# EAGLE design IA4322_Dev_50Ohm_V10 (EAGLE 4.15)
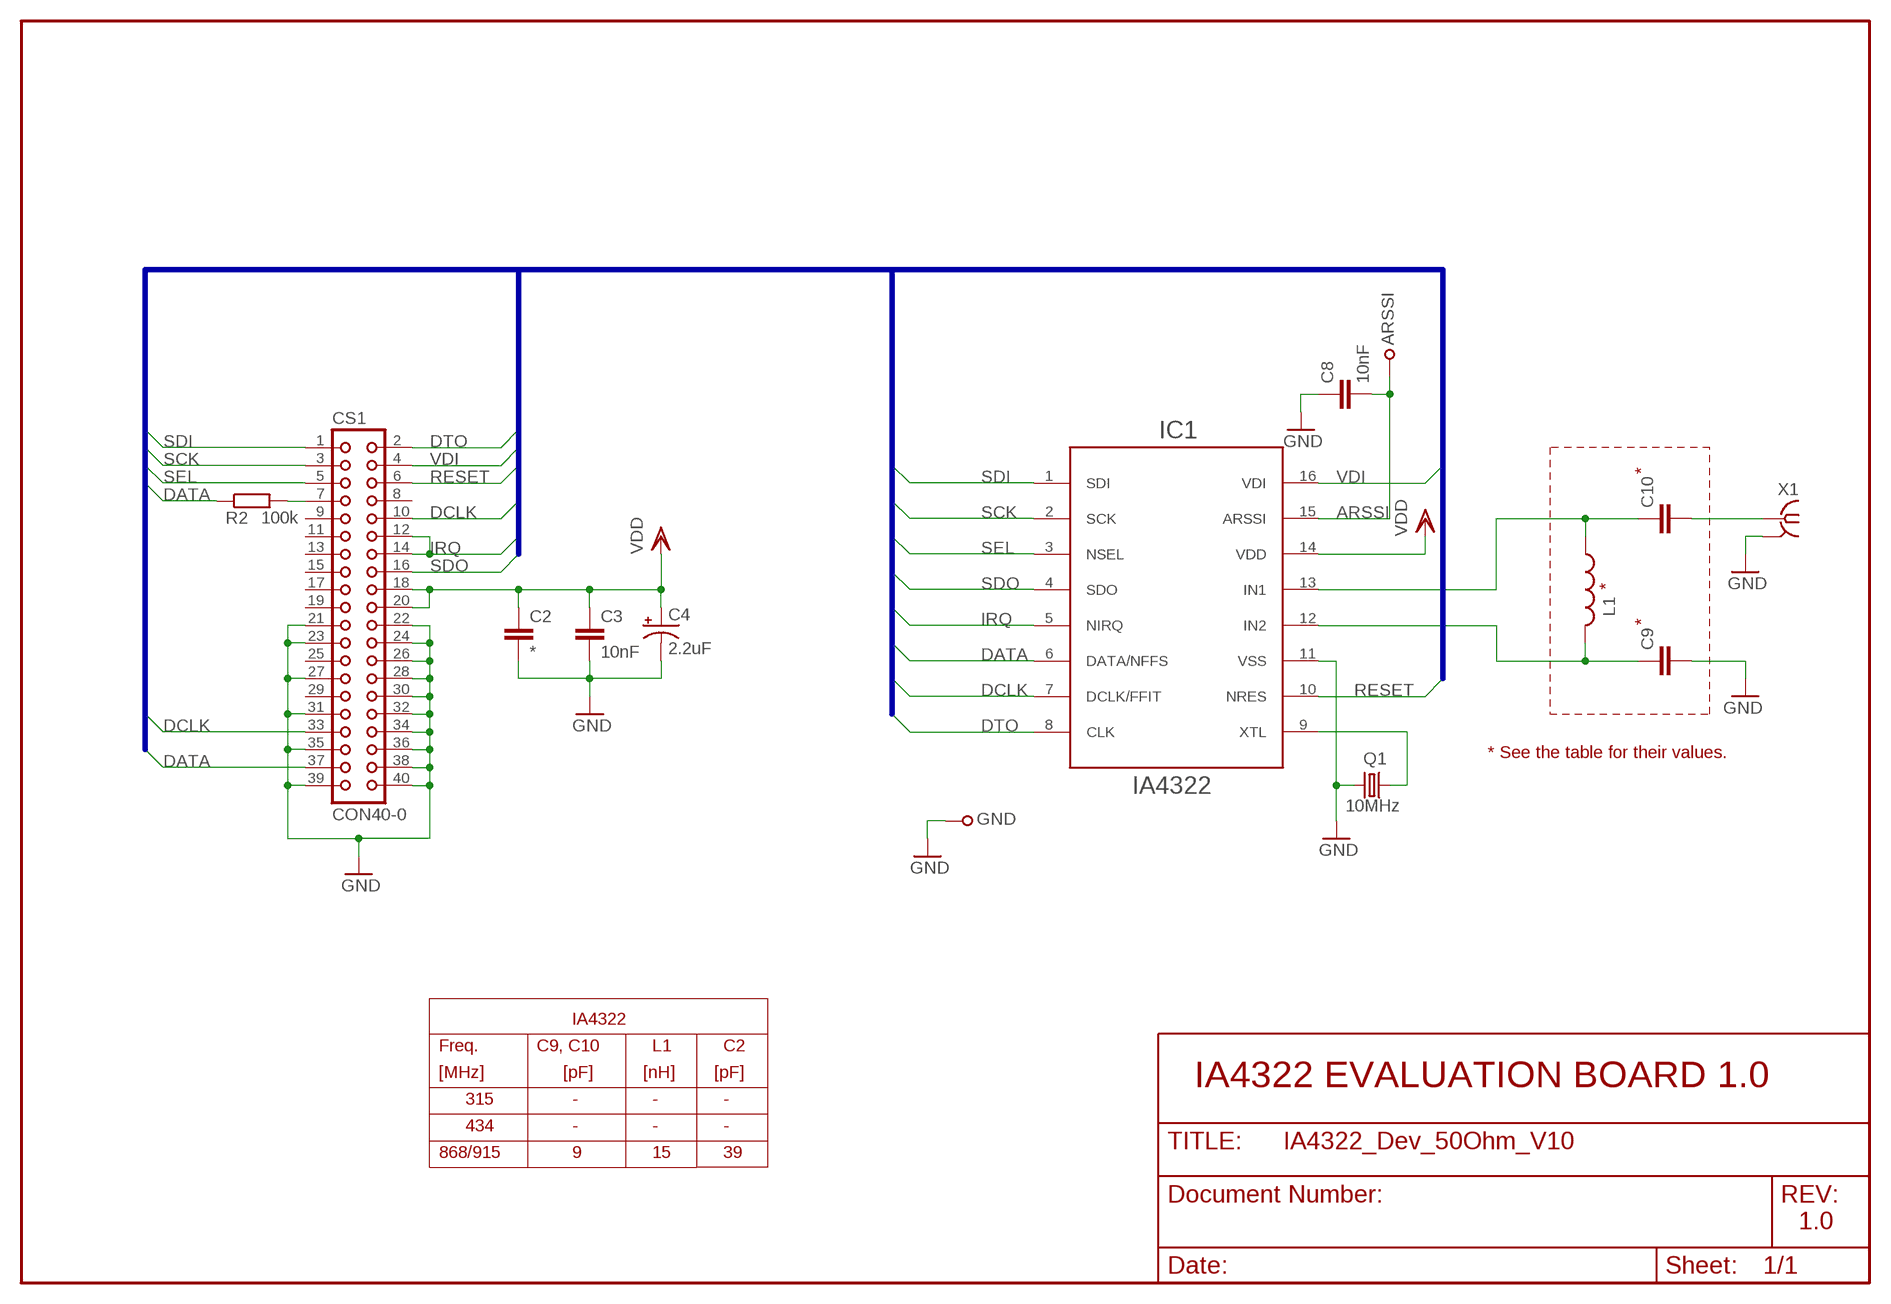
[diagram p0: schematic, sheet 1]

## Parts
ARSSI  TESTPOINT  TESTPOINT39MIL  [TESTPOINT1,0]
C2  *  C-EUC0603  [C0603]
C3  10nF  C-EUC0603  [C0603]
C4  2.2uF  CPOL-USA/3216-18R  [A/3216-18R]
C8  10nF  C-EUC0603  [C0603]
C9  C-EUC0603  [C0603]
C10  C-EUC0603  [C0603]
CS1  CON40-0  [PANDUIT-057-040-0-INTEGRATION]
GND  TESTPOINT39MIL  [TESTPOINT1,0]
IC1  IA4322  RITATSSOP-16(NEW)  [TSSOP-16(NEW)]
L1  INDUCTCOILCRAFT-0603  [L1608]
Q1  10MHz  CRYTALSM49  [SM49]
R2  100k  R-EU_R0603  [R0603]
X1  BU-SMA-H  [BU-SMA-H]

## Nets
ARSSI: ARSSI.1 C8.2 IC1.15(ARSSI)
DATA: CS1.37 IC1.6(DATA/NFFS) R2.1
DCLK: CS1.10 CS1.33 IC1.7(DCLK/FFIT)
DTO: CS1.2 IC1.8(CLK)
GND: C2.2 C3.2 C4.- C8.1 C9.2 CS1.21 CS1.22 CS1.23 CS1.24 CS1.26 CS1.27 CS1.28 CS1.30 CS1.31 CS1.32 CS1.34 CS1.35 CS1.36 CS1.38 CS1.39 CS1.40 GND.1 IC1.11(VSS) Q1.2 X1.2(GND)
IRQ: CS1.12 CS1.14 IC1.5(NIRQ)
N$1: CS1.7 R2.2
N$2: C10.1 IC1.13(IN1) L1.2
N$3: C9.1 IC1.12(IN2) L1.1
N$4: IC1.9(XTL) Q1.1
N$8: C10.2 X1.1
RESET: CS1.6 IC1.10(NRES)
SCK: CS1.3 IC1.2(SCK)
SDI: CS1.1 IC1.1(SDI)
SDO: CS1.16 IC1.4(SDO)
SEL: CS1.5 IC1.3(NSEL)
VDD: C2.1 C3.1 C4.+ CS1.18 CS1.20 IC1.14(VDD)
VDI: CS1.4 IC1.16(VDI)
Unconnected: CS1.8 CS1.9 CS1.11 CS1.13 CS1.15 CS1.17 CS1.19 CS1.25 CS1.29

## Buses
B$1

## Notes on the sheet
- *
- *
- *
- * See the table for their values.
- IA4322
- Freq. | C9, C10 | L1 | C2
- [MHz] | [pF] | [nH] | [pF]
- IA4322 EVALUATION BOARD 1.0
- 315 | - | - | -
- 434 | - | - | -
- 868/915 | 9 | 15 | 39
- 1.0

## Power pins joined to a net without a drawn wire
GND: X1.3(GND) X1.4(GND) X1.5(GND)

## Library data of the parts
ARSSI GND = lve:TESTPOINT
C2 C3 C8-C10 = rcl:C-EU: CAPACITOR, European symbol
C4 = rcl:CPOL-US: POLARIZED CAPACITOR, American symbol
CS1 = lve:CON40
IC1 = lve:RITA: RITA
L1 = lve:INDUCT
Q1 = crystal:CRYTAL: CRYSTAL
R2 = rcl:R-EU_: RESISTOR, European symbol
X1 = con-coax:BU-SMA-H: FEMALE SMA CONNECTOR Radiall distributor RS 193-9325

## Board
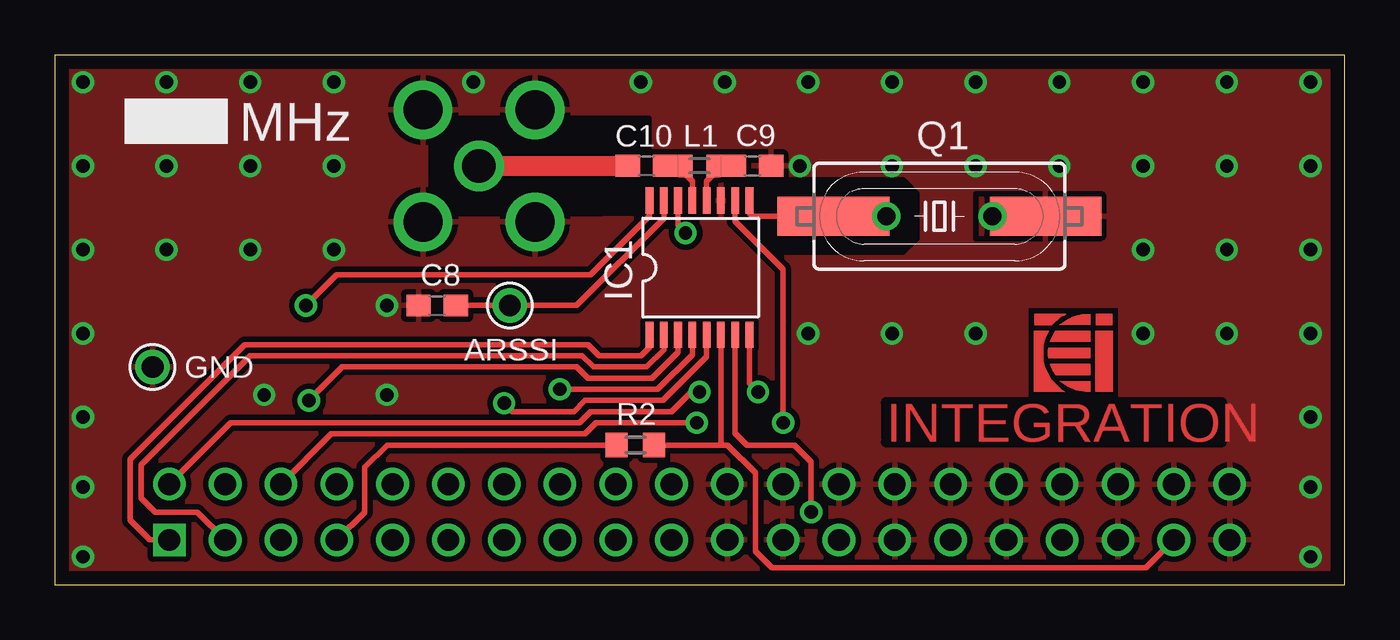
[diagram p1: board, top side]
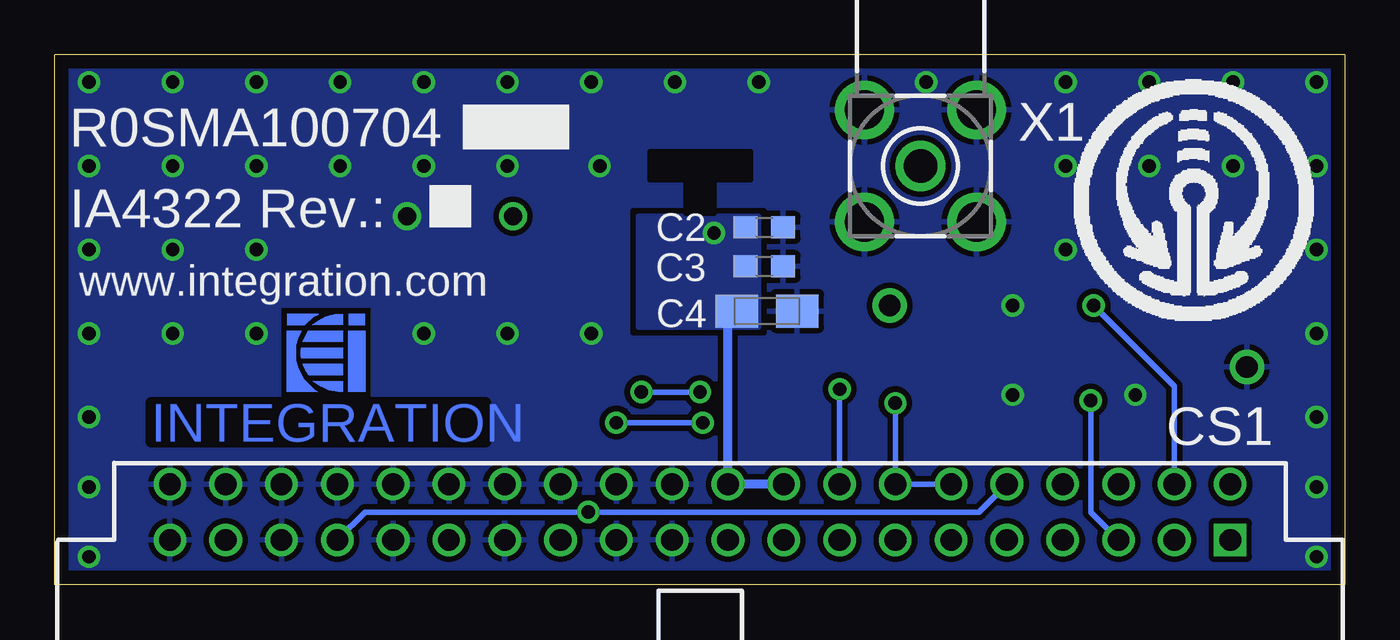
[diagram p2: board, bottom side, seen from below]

Size 58.7 x 24.1 mm. Coordinates in mm from the lower left corner, seen from the top.
Outline: 0,0 58.7,0 58.7,24.1 0,24.1 0,0
Copper layers (1*16): Top 0.035mm / dielectric 1.5mm / Bottom 0.035mm
Design rules "default_INTEGRATION": minimum track width 10mil, minimum drill 24mil, track to track 10mil, track to pad 10mil, pad to pad 10mil, via to via 10mil, smd to smd 10mil, copper to edge 25mil, drill to drill 8mil, minimum pad ring 8mil, minimum via ring 8mil, stop-mask expansion 4mil, vias tented up to drill 24mil, thermal gap 10mil
tRestrict: area 17,16.8 to 24.9,21.3; 14 lines
bRestrict: 10 lines

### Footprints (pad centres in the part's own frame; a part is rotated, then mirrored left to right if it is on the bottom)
TESTPOINT1,0 = drill 0.991 pad 1.575 round: 1 0,0
C0603 = smd 1.1 x 1: 1 -0.85,0; 2 0.85,0
A/3216-18R = smd 1.95 x 1.5: + 1.375,0; - -1.375,0
PANDUIT-057-040-0-INTEGRATION = drill 0.991 square: 1 -24.13,-1.27 | drill 0.991 round: 2 -24.13,-3.81; 3 -21.59,-1.27; 4 -21.59,-3.81; 5 -19.05,-1.27; 6 -19.05,-3.81; 7 -16.51,-1.27; 8 -16.51,-3.81; 9 -13.97,-1.27; 10 -13.97,-3.81; 11 -11.43,-1.27; 12 -11.43,-3.81; 13 -8.89,-1.27; 14 -8.89,-3.81; 15 -6.35,-1.27; 16 -6.35,-3.81; 17 -3.81,-1.27; 18 -3.81,-3.81; 19 -1.27,-1.27; 20 -1.27,-3.81; 21 1.27,-1.27; 22 1.27,-3.81; 23 3.81,-1.27; 24 3.81,-3.81; 25 6.35,-1.27; 26 6.35,-3.81; 27 8.89,-1.27; 28 8.89,-3.81; 29 11.43,-1.27; 30 11.43,-3.81; 31 13.97,-1.27; 32 13.97,-3.81; 33 16.51,-1.27; 34 16.51,-3.81; 35 19.05,-1.27; 36 19.05,-3.81; 37 21.59,-1.27; 38 21.59,-3.81; 39 24.13,-1.27; 40 24.13,-3.81
TSSOP-16(NEW) = smd 1.2 x 0.35: 1 -3.107,2.275; 2 -3.107,1.625; 3 -3.107,0.975; 4 -3.107,0.325; 5 -3.107,-0.325; 6 -3.107,-0.975; 7 -3.107,-1.625; 8 -3.107,-2.275; 9 2.993,-2.275; 10 2.993,-1.625; 11 2.993,-0.975; 12 2.993,-0.325; 13 2.993,0.325; 14 2.993,0.975; 15 2.993,1.625; 16 2.993,2.275
L1608 = smd 0.64 x 1.02: 1 -0.64,0; 2 0.64,0
SM49 = smd 5.08 x 1.778: 1 -4.826,0; 2 4.826,0
R0603 = smd 1 x 1.1: 1 -0.85,0; 2 0.85,0
BU-SMA-H = drill 1.524 round: 1 0,0 | drill 1.778 round: 2 -2.55,2.55; 3 2.55,2.55; 4 2.55,-2.55; 5 -2.55,-2.55

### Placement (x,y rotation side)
ARSSI  20.7,12.7 0 top
C2  26.42,16.26 0 bottom
C3  26.42,14.48 0 bottom
C4  26.29,12.45 180 bottom
C8  17.4,12.7 0 top
C9  31.75,19.05 0 top
C10  26.92,19.05 180 top
CS1  29.34,0.76 180 bottom
GND  4.45,9.91 0 top
IC1  29.34,14.48 90 top
L1  29.34,19.05 180 top
Q1  40.26,16.76 0 top
R2  26.42,6.35 180 top
U$1  [RECEIVE-ICON06]  6.86,17.78 0 bottom
U$2  [LOGO-SMALL]  46.35,10.54 0 top
U$3  [LOGO-SMALL]  46.35,10.54 0 bottom
X1  19.3,19.05 90 bottom

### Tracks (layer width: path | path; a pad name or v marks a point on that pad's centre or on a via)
ARSSI
  Top 0.254: IC1.15 27.71,16.66 23.75,12.7 ARSSI.1 C8.2
DATA
  Top 0.254: R2.1 27.27,6.4 | R2.1 30.31,6.35 | R2.1 27.27,6.3 | CS1.37 49.66,0.76 32.64,0.76 31.88,1.52 31.88,5.08 30.61,6.35 30.31,6.35 | 30.31,6.35 IC1.6
DCLK  (via drill 0.61 pad 1.02)
  Top 0.254: v34.42,3.3 34.42,5.59 33.66,6.35 31.5,6.35 30.96,6.88 IC1.7
  Bottom 0.254: CS1.10 16.64,3.3 v34.42,3.3 44.58,3.3 CS1.33
DTO  (via drill 0.61 pad 1.02)
  Top 0.254: CS1.2 8,7.37 23.88,7.37 24.38,7.87 28.07,7.87 28.96,8.76 v29.34,8.76 | IC1.8 31.61,9.15 v32,8.76
  Bottom 0.254: v29.34,8.76 v32,8.76
GND  (via drill 0.61 pad 1.02, 0.81 pad 1.27)
  other vias: 15.11,12.7 42.67,16.76 33.91,19.05 1.27,22.86 5.08,22.86 8.89,22.86 12.7,22.86 19.05,22.86 1.27,19.05 1.27,15.24 1.27,11.43 1.27,7.62 1.27,1.27 1.27,4.45 5.08,19.05 5.08,15.24 8.89,15.24 8.89,19.05 12.7,19.05 12.7,15.24 57.15,22.86 57.15,19.05 57.15,15.24 57.15,11.43 57.15,7.62 57.15,1.27 53.34,22.86 49.53,22.86 45.72,22.86 41.91,22.86 38.1,22.86 34.29,22.86 30.48,22.86 26.67,22.86 53.34,19.05 49.53,19.05 45.72,19.05 41.91,19.05 38.1,19.05 53.34,15.24 49.53,15.24 53.34,11.43 49.53,11.43 41.91,11.43 38.1,11.43 34.29,11.43 57.15,4.45 15.11,8.64 9.53,8.64
  pour Bottom (rank 2): 0,0 0,23.94 58.48,23.94 58.48,0
  pour Top (rank 2): 0,0 0,23.94 58.48,23.94 58.48,0
IRQ  (via drill 0.61 pad 1.02)
  Top 0.254: IC1.5 29.66,10.36 27.69,8.38 24.13,8.38 23.62,7.87 20.83,7.87 v20.45,8.26
  Bottom 0.254: CS1.12 CS1.14 v20.45,8.26
N$1
  Top 0.254: R2.2 15.11,6.35 14.1,5.33 14.1,3.3 CS1.7
N$2
  Top 0.254: IC1.13 29.01,18.36 28.7,18.67 L1.2 28.45,19.05
  Top 1.016: C10.1 28.45,19.05
N$3
  Top 0.254: IC1.12 29.66,18.36 29.97,18.67 29.98,18.67 L1.1 30.35,19.05
  Top 1.016: 30.35,19.05 C9.1
N$4  (via drill 0.81 pad 1.27)
  Top 0.254: IC1.9 31.61,16.9 31.75,16.76 Q1.1 v37.85,16.76
N$8
  Top 0.92: X1.1 C10.2
RESET  (via drill 0.61 pad 1.02)
  Top 0.254: CS1.6 12.57,6.86 24.13,6.86 24.64,7.37 v29.21,7.37 | IC1.10 30.96,16.54 33.15,14.35 v33.15,7.37
  Bottom 0.254: v29.21,7.37 v33.15,7.37
SCK
  Top 0.254: CS1.3 6.48,3.3 4.57,3.3 3.94,3.94 3.94,5.46 8.89,10.41 24,10.41 24.51,9.91 26.92,9.91 27.71,10.69 IC1.2
SDI
  Top 0.254: CS1.1 4.32,2.03 3.43,2.92 3.43,5.71 8.64,10.92 24.26,10.92 24.77,10.41 26.67,10.41 27.06,10.81 IC1.1
SDO  (via drill 0.61 pad 1.02)
  Top 0.254: IC1.4 29.01,10.47 27.43,8.89 v22.99,8.89
  Bottom 0.254: CS1.16 v22.99,8.89
SEL  (via drill 0.61 pad 1.02)
  Top 0.254: IC1.3 28.36,10.58 27.18,9.4 24.26,9.4 23.75,9.91 13.08,9.91 v11.56,8.38
  Bottom 0.254: CS1.5 11.56,3.3 v11.56,8.38
VDD  (via drill 0.61 pad 1.02)
  Top 0.254: IC1.14 28.36,16.34 v28.7,16
  Bottom 0.406: CS1.18 CS1.20 28.07,12.19
  pour Bottom (no thermals): 26.67,16.76 32.13,16.76 32.13,11.71 26.67,11.71
VDI  (via drill 0.61 pad 1.02)
  Top 0.254: IC1.16 27.06,16.77 24.38,14.1 12.83,14.1 v11.43,12.7
  Bottom 0.254: v11.43,12.7 7.75,9.02 CS1.4

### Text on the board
Top: INTEGRATION
Bottom: INTEGRATION
tPlace: MHz
bPlace: R0SMA100704 | IA4322 Rev.: | www.integration.com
